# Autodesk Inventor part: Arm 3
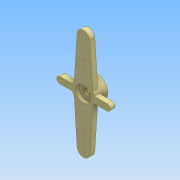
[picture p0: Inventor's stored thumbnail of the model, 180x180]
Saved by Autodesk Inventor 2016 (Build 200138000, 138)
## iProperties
Created: 2016-01
Part Number: Arm 3
Material: Нейлон 6/6
Document SubType Name: Modeling
Designer: Evgeny
Density: 1.13 g/cm^3
Appearance: Нейлон 6
Author: Evgeny
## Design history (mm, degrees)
sketch "Эскиз1"
  geometry: L1 (1.996, 15.132)-(2.867, 2.008); L2 (-1.996, 15.132)-(-2.867, 2.008); L3 (2.867, 2.008)-(3, 0); L4 (-2.867, 2.008)-(-3, 0); L5 (-13.698, 0)-(13.244, 0); L6 (1.996, -15.132)-(2.867, -2.008); L7 (-1.996, -15.132)-(-2.867, -2.008); L8 (-2.867, -2.008)-(-3, 0); L9 (2.867, -2.008)-(3, 0); L10 (7.25, 1)-(3.354, 1); L11 (-3.354, 1)-(-7.25, 1); L12 (7.25, -1)-(3.354, -1); L13 (-3.354, -1)-(-7.25, -1); C1 r 1 at (0, 0); C2 r 0.25 at (0, 15); C3 r 0.25 at (0, 13); C4 r 0.25 at (0, 11); C5 r 0.25 at (0, 9); C6 r 0.25 at (0, 7); C7 r 0.25 at (0, 5); C8 r 0.25 at (0, -5); C9 r 0.25 at (0, -7); C10 r 0.25 at (0, -9); C11 r 0.25 at (0, -11); C12 r 0.25 at (0, -13); C13 r 0.25 at (0, -15); C14 r 0.25 at (7.25, 0); C15 r 0.25 at (-7.25, 0); C16 r 0.25 at (-5.25, 0); C17 r 0.25 at (5.25, 0); A1 r 2 centre (0, 15) between (1.996, 15.132) and (-1.996, 15.132); A2 r 2 centre (0, -15) between (-1.996, -15.132) and (1.996, -15.132); A3 r 1 centre (7.25, 0) between (7.25, -1) and (7.25, 1); A4 r 1 centre (-7.25, 0) between (-7.25, 1) and (-7.25, -1); A5 r 3.5 centre (0, 0) between (2.867, -2.008) and (3.354, -1); A6 r 3.5 centre (0, 0) between (3.354, 1) and (2.867, 2.008); A7 r 3.5 centre (0, 0) between (-2.867, 2.008) and (-3.354, 1); A8 r 3.5 centre (0, 0) between (-3.354, -1) and (-2.867, -2.008); 1 further point
  constraints: 26 end point, 25 centre point, 16 point on circle, 11 symmetric about line, 6 coincident, 6 tangent, 5 point on line, 5 vertical alignment, 2 horizontal alignment, 2 parallel, 1 horizontal, 7 other
  dimensions: "d1" = 2 diameter of C1; "d2" = 3 distance of L3.end point (0, 0); "d3" = 3 distance of L4.end point (0, 0); "d4" = 15 distance of A1.centre point (0, 0); "d5" = 2 radius of A1; "d6" = 0.5 diameter of C2; "d7" = 0.5 diameter of C3 (= d6); "d8" = 0.5 diameter of C4 (= d6); "d9" = 0.5 diameter of C5 (= d6); "d10" = 0.5 diameter of C6 (= d6); "d11" = 0.5 diameter of C7 (= d6); "d13" = 2 distance of C3.centre A1.centre; "d14" = 2 distance of C4.centre C3.centre; "d15" = 2 distance of C5.centre C4.centre; "d16" = 2 distance of C6.centre C5.centre; "d17" = 2 distance of C7.centre C6.centre; "d32" = 2 diameter of A3; "d33" = 2 diameter of A4; "d34" = 14.5 distance of A4.centre A3.centre; "d35" = 7.25 distance of point (0, 0) A3.centre (= 0.5 x d34); "d36" = 0.5 diameter of C14; "d37" = 0.5 diameter of C15; "d38" = 0.5 diameter of C16; "d39" = 0.5 diameter of C17; "d40" = 2 distance of C16.centre A4.centre; "d41" = 2 distance of C17.centre C14.centre
extrude "Выдавливание1" new body sketch "Эскиз1" distance "d19" = 1.5; taper "d20" = 0 deg
sketch "Эскиз2"
  geometry: C1 r 1 at (0, 0) reference; C2 r 3.5 at (0, 0); A1 r 3.5 centre (0, 0) between (2.867, -2.008) and (-3.354, 1) reference; 2 further points
  constraints: 1 centre point, 1 coincident, 1 concentric
extrude "Выдавливание2" join sketch "Эскиз2" distance "d21" = 2.5; taper "d22" = 0 deg
sketch "Эскиз3"
  geometry: C1 r 1 at (0, 0) reference; C2 r 2.25 at (0, 0); 1 further point
  constraints: 1 centre point, 1 coincident
  dimensions: "d23" = 4.5 diameter of C2
extrude "Выдавливание3" cut sketch "Эскиз3" distance "d24" = 2; taper "d25" = 0 deg
sketch "Эскиз4"
  geometry: C1 r 2.4 at (0, 0); 1 further point
  constraints: 1 centre point, 1 coincident
  dimensions: "d29" = 4.8 diameter of C1
extrude "Выдавливание4" cut sketch "Эскиз4" distance "d30" = 1; taper "d31" = 0 deg
node "Твердое тело1"
other parameters: "d0" = 7
